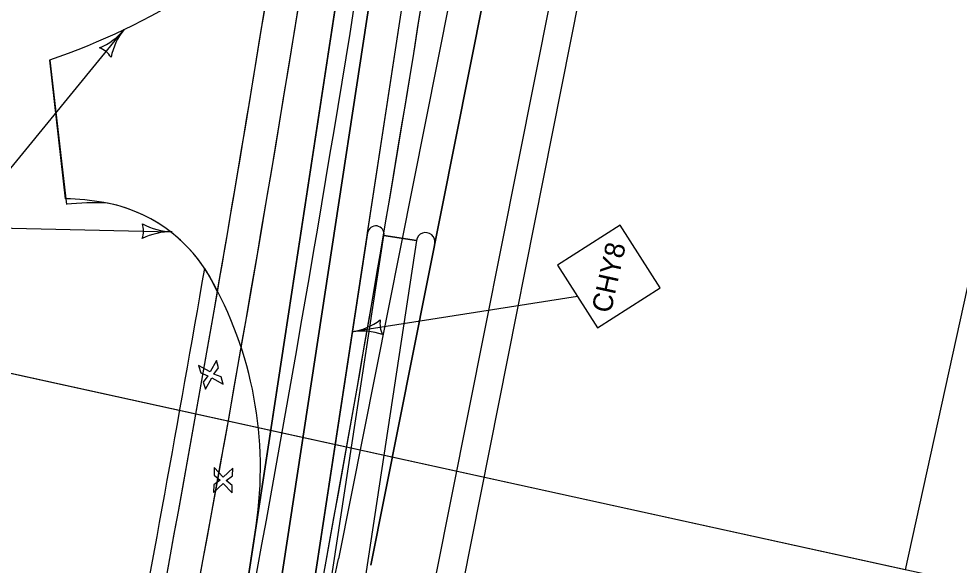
# Model space of a CAD drawing. Extents: x 14104283 to 14129344, y 8637090 to 8673339.
# Drawn here: x 14107822.5 to 14108164.1, y 8639738.3 to 8639937 of the extents above; entities that cross this region are included whole.
import ezdxf

# ---------------------------------------------------------------- set-up
doc = ezdxf.new("R2010")
doc.units = 0
for name, color, linetype in [('Cell', 7, 'Continuous'), ('Default', 7, 'Continuous'), ('dsn_stg_shd_prev', 7, 'Continuous'), ('dsnNonPlotable', 7, 'Continuous'), ('dsnPaintPlaceBrokenLineWhite', 7, 'Continuous'), ('dsnPaintPlaceChannelizingLaneYellow', 7, 'Continuous'), ('dsnPaintPlaceEdgeLineRightWhite', 7, 'Continuous'), ('dsnStdLabel', 7, 'Continuous'), ('dsnStgShadingPrevPav', 7, 'Continuous')]:
    doc.layers.add(name, color=color, linetype=linetype)

msp = doc.modelspace()

# ---------------------------------------------------------------- linework, layer by layer
at = {"layer": 'Cell'}
for p, q in [((14107894.33, 8639812.75), (14107892.01, 8639808.57)), ((14107895.09, 8639810.1), (14107894.33, 8639812.75)), ((14107892.01, 8639808.57), (14107887.84, 8639810.89)), ((14107887.84, 8639810.89), (14107888.6, 8639808.24)), ((14107888.6, 8639808.24), (14107891.24, 8639807.18)), ((14107893.4, 8639807.8), (14107895.09, 8639810.1)), ((14107891.24, 8639807.18), (14107889.56, 8639804.88)), ((14107889.56, 8639804.88), (14107890.32, 8639802.24)), ((14107890.32, 8639802.24), (14107892.63, 8639806.41)), ((14107892.63, 8639806.41), (14107896.81, 8639804.09)), ((14107896.05, 8639806.74), (14107893.4, 8639807.8)), ((14107896.81, 8639804.09), (14107896.05, 8639806.74)), ((14107893.54, 8639773.76), (14107893.45, 8639771.01)), ((14107896.8, 8639770.27), (14107893.54, 8639773.76)), ((14107893.45, 8639771.01), (14107895.64, 8639769.19)), ((14107900.29, 8639773.53), (14107896.8, 8639770.27)), ((14107897.89, 8639769.11), (14107900.2, 8639770.79)), ((14107900.2, 8639770.79), (14107900.29, 8639773.53)), ((14107893.24, 8639764.76), (14107896.73, 8639768.02)), ((14107893.33, 8639767.51), (14107893.24, 8639764.76)), ((14107895.64, 8639769.19), (14107893.33, 8639767.51)), ((14107896.73, 8639768.02), (14107899.99, 8639764.54)), ((14107900.08, 8639767.29), (14107897.89, 8639769.11)), ((14107899.99, 8639764.54), (14107900.08, 8639767.29))]:
    msp.add_line(p, q, dxfattribs=at)
at = {"layer": 'Default'}
for p, q in [((14107990.79, 8640290.82), (14107885.22, 8639598.83)), ((14107885.37, 8639599.61), (14107990.94, 8640291.61)), ((14108002.8, 8640289.8), (14107897.23, 8639597.8)), ((14107908.95, 8639595.21), (14108014.52, 8640287.2)), ((14108004.96, 8640013.11), (14107950.42, 8639738.27)), ((14108004.96, 8640013.11), (14107973.63, 8639855.23)), ((14107973.96, 8639733.6), (14108028.5, 8640008.43)), ((14107949.24, 8639859.12), (14107967.08, 8639976.1)), ((14107937.44, 8639940.91), (14107908.71, 8639752.63)), ((14107839.51, 8639871.5), (14107833.76, 8639922)), ((14107897.98, 8639483.38), (14107955.17, 8639858.22)), ((14107967.03, 8639856.41), (14107944.41, 8639708.12)), ((14107967.03, 8639856.41), (14107955.17, 8639858.22)), ((14107955.17, 8639858.22), (14107967.03, 8639856.41))]:
    msp.add_line(p, q, dxfattribs=at)
for centre, radius, start, end in [((14107752.7, 8640158.5), 250, 288.9195, 302.3186), ((14107838.11, 8639781.51), 90, 80.198, 89.1076), ((14107844.07, 8639816), 55, 29.809, 80.198), ((14107952.2, 8639858.67), 3, 351.326, 171.326), ((14107970.34, 8639855.88), 3.35, 348.776, 171.0218), ((14107770.31, 8639773.74), 140, 351.326, 29.809)]:
    msp.add_arc(centre, radius, start, end, dxfattribs=at)
at = {"layer": 'dsn_stg_shd_prev'}
for p, q in [((14108038.31, 8640006.49), (14107983.77, 8639731.65)), ((14107950.42, 8639738.27), (14107992.68, 8639951.24))]:
    msp.add_line(p, q, dxfattribs=at)
at = {"layer": 'dsnNonPlotable'}
for points in [[(14107490.45, 8639880.3), (14107826.84, 8641411.28), (14108813.31, 8641194.53), (14108476.92, 8639663.55)], [(14107651.31, 8639844.94), (14107987.7, 8641375.92), (14108480.93, 8641267.54), (14108144.54, 8639736.56)]]:
    msp.add_lwpolyline(points, close=True, dxfattribs=at)
at = {"layer": 'dsnPaintPlaceBrokenLineWhite'}
msp.add_line((14107897.23, 8639597.8), (14108002.8, 8640289.8), dxfattribs=at)
at = {"layer": 'dsnPaintPlaceChannelizingLaneYellow'}
msp.add_line((14107949.24, 8639859.13), (14107909.1, 8639596), dxfattribs=at)
at = {"layer": 'dsnPaintPlaceEdgeLineRightWhite'}
msp.add_line((14107908.71, 8639752.63), (14107885.37, 8639599.61), dxfattribs=at)
for centre, radius, start, end in [((14107752.7, 8640158.5), 250, 288.9195, 302.3186), ((14107838.11, 8639781.51), 90, 80.198, 89.1076), ((14107844.07, 8639816), 55, 29.809, 80.198), ((14107770.31, 8639773.74), 140, 351.326, 29.809)]:
    msp.add_arc(centre, radius, start, end, dxfattribs=at)
at = {"layer": 'dsnStdLabel'}
for p, q in [((14107802.08, 8639861.24), (14107860.8, 8639933.07)), ((14107802.08, 8639861.24), (14107878.22, 8639859.5)), ((14108025.51, 8639836.03), (14107943.57, 8639823.14))]:
    msp.add_line(p, q, dxfattribs=at)
msp.add_lwpolyline([(14108032.78, 8639824.65), (14108055.53, 8639839.2), (14108040.98, 8639861.95), (14108018.23, 8639847.4)], close=True, dxfattribs=at)
for centre, radius, start, end in [((14107843.03, 8639947.6), 22.95, 292.6641, 320.7354), ((14107878.57, 8639918.55), 22.95, 140.7352, 168.8065), ((14107848.62, 8639918.18), 8.86, 33.0011, 68.4695), ((14107858.98, 8639859.94), 8.86, 340.9615, 16.4299), ((14107877.69, 8639836.56), 22.95, 88.6957, 116.7669), ((14107878.74, 8639882.45), 22.95, 240.6245, 268.6958), ((14107940, 8639845.81), 22.95, 278.9373, 307.0086), ((14107962.58, 8639826.13), 8.86, 171.2032, 206.6716), ((14107947.13, 8639800.47), 22.95, 70.8662, 98.9375)]:
    msp.add_arc(centre, radius, start, end, dxfattribs=at)
at = {"layer": 'dsnStgShadingPrevPav'}
for p, q in [((14107993.19, 8640015.44), (14107938.65, 8639740.6)), ((14107993.19, 8640015.44), (14107938.65, 8639740.6)), ((14107950.42, 8639738.27), (14108004.96, 8640013.11)), ((14107833.76, 8639922), (14107839.82, 8639869.51))]:
    msp.add_line(p, q, dxfattribs=at)
for centre, radius, start, end in [((14098576.76, 8641447.78), 9456, 348.449343, 351.672846), ((14098576.76, 8641447.78), 9468, 347.807255, 351.672846), ((14098576.76, 8641447.78), 9468, 348.194582, 351.672846), ((14098576.76, 8641447.78), 9488, 348.202524, 351.672846), ((14098576.76, 8641447.78), 9488, 348.202524, 351.672846), ((14098576.76, 8641447.78), 9512, 348.176197, 351.653537), ((14098576.76, 8641447.78), 9512, 348.212012, 351.653537), ((14098576.76, 8641447.78), 9456, 350.195701, 351.23682), ((14107752.7, 8640158.5), 250, 288.9195, 302.3186), ((14107849.81, 8639782.85), 87.24, 86.7296, 96.5795), ((14107844.07, 8639816), 55, 23.1027, 78.7566), ((14098576.76, 8641447.78), 9450, 348.220778, 350.242299), ((14107844.07, 8639816), 55, 23.1027, 33.2753), ((14098576.76, 8641447.78), 9456, 348.449343, 350.195701), ((14089678.7, 8643364.11), 18616, 348.014807, 348.776036), ((14089678.7, 8643364.11), 18616, 348.014807, 348.776036)]:
    msp.add_arc(centre, radius, start, end, dxfattribs=at)

# ---------------------------------------------------------------- texts
at = {"layer": 'dsnStdLabel'}
msp.add_text('CHY8', height=7.2, rotation=77.6078, dxfattribs=at).set_placement((14108037.57, 8639829.64))

doc.saveas('drawing.dxf')
